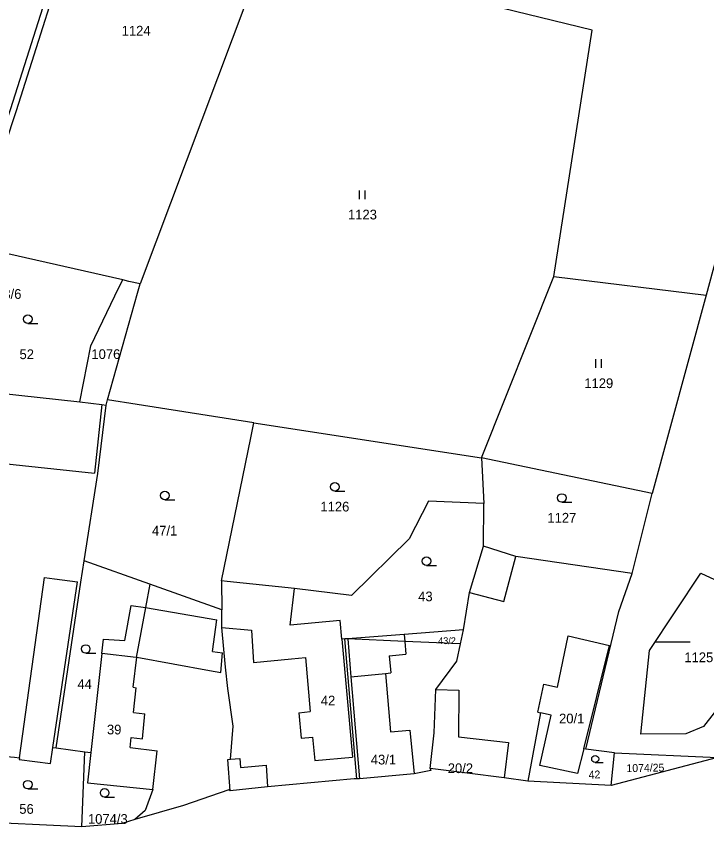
# Model space of a CAD drawing. Extents: x -746176 to -739709, y -1127410 to -1124482.
# Drawn here: x -742233.7 to -742113, y -1126052.3 to -1125910.5 of the extents above; entities that cross this region are included whole.
import ezdxf

# ---------------------------------------------------------------- set-up
doc = ezdxf.new("R2010")
doc.units = 0
for name, color, linetype in [('Hranice parcel', 7, 'Continuous'), ('Parcelní čísla', 7, 'Continuous'), ('Vnitřní kresba', 7, 'Continuous'), ('Značky kultur', 7, 'Continuous')]:
    doc.layers.add(name, color=color, linetype=linetype)

msp = doc.modelspace()

# ---------------------------------------------------------------- linework, layer by layer
at = {"layer": 'Hranice parcel'}
for p, q in [((-742190.21, -1125899.2), (-742212.05, -1125957.33)), ((-742110.2, -1125948.49), (-742113.1, -1125959.31)), ((-742215.07, -1125956.62), (-742241.51, -1125950.63)), ((-742152.36, -1125987.76), (-742139.76, -1125956.04)), ((-742139.76, -1125956.04), (-742113.1, -1125959.31)), ((-742113.1, -1125959.31), (-742122.54, -1125993.99)), ((-742246.94, -1125975.25), (-742222.55, -1125977.95)), ((-742217.96, -1125978.51), (-742217.71, -1125977.62)), ((-742192.16, -1125981.6), (-742152.36, -1125987.76)), ((-742122.54, -1125993.99), (-742152.36, -1125987.76)), ((-742152.36, -1125987.76), (-742151.94, -1125995.7)), ((-742126.05, -1126007.96), (-742122.54, -1125993.99)), ((-742152.03, -1126003.21), (-742151.94, -1125995.7)), ((-742210.31, -1126009.86), (-742221.81, -1126005.78)), ((-742197.79, -1126009.24), (-742197.78, -1126014.31)), ((-742197.78, -1126014.31), (-742210.31, -1126009.86)), ((-742156.03, -1126020.28), (-742155.5, -1126017.83)), ((-742174.18, -1126043.87), (-742176.24, -1126019.4)), ((-742156.03, -1126020.28), (-742165.79, -1126019.86)), ((-742226.7, -1126038.48), (-742221.69, -1126039.15)), ((-742222.2, -1126052.27), (-742221.69, -1126039.15)), ((-742221.69, -1126039.15), (-742220.66, -1126039.29)), ((-742129.13, -1126039.33), (-742134.12, -1126038.69)), ((-742129.74, -1126045.05), (-742129.13, -1126039.33)), ((-742129.13, -1126039.33), (-742111.14, -1126040.16)), ((-742111.14, -1126040.16), (-742129.74, -1126045.05)), ((-742148.42, -1126043.69), (-742161.35, -1126042.09)), ((-742144.3, -1126044.3), (-742148.42, -1126043.69)), ((-742129.74, -1126045.05), (-742144.3, -1126044.3))]:
    msp.add_line(p, q, dxfattribs=at)
for points in [[(-742241.51, -1125950.63), (-742233.66, -1125926.96), (-742223.23, -1125894.07), (-742218.91, -1125880.44), (-742217.69, -1125875.07), (-742216.33, -1125869.06)], [(-742239.87, -1125941.89), (-742234.61, -1125926.63), (-742224.19, -1125893.77)], [(-742139.76, -1125956.04), (-742133.02, -1125912.95), (-742184.93, -1125900.23)], [(-742222.55, -1125977.95), (-742220.67, -1125968.16), (-742215.73, -1125957.97), (-742215.07, -1125956.62)], [(-742212.05, -1125957.33), (-742213.99, -1125956.87), (-742215.07, -1125956.62)], [(-742217.71, -1125977.62), (-742212.49, -1125958.92), (-742212.05, -1125957.33)], [(-742222.55, -1125977.95), (-742218.7, -1125978.38), (-742217.96, -1125978.51)], [(-742192.16, -1125981.6), (-742212.57, -1125978.42), (-742217.71, -1125977.62)], [(-742221.81, -1126005.78), (-742219.41, -1125990.5), (-742217.96, -1125978.51)], [(-742197.79, -1126009.24), (-742192.7, -1125984.26), (-742192.16, -1125981.6)], [(-742151.94, -1125995.7), (-742161.62, -1125995.29), (-742165.01, -1126001.93), (-742175.08, -1126011.79), (-742185.07, -1126010.6)], [(-742155.5, -1126017.83), (-742154.46, -1126011.3), (-742152.03, -1126003.21)], [(-742126.05, -1126007.96), (-742146.39, -1126004.99), (-742152.03, -1126003.21)], [(-742226.7, -1126038.48), (-742222.39, -1126009.48), (-742221.81, -1126005.78)], [(-742134.12, -1126038.69), (-742128.4, -1126014.62), (-742126.05, -1126007.96)], [(-742102.49, -1126016.08), (-742109.85, -1126029.96), (-742113.56, -1126034.73), (-742116.68, -1126036.01), (-742124.54, -1126036.07), (-742122.99, -1126021.43), (-742114.02, -1126007.91), (-742106.36, -1126011.45), (-742102.49, -1126016.08)], [(-742185.07, -1126010.6), (-742196.8, -1126009.35), (-742197.79, -1126009.24)], [(-742210.31, -1126009.86), (-742211.09, -1126013.94), (-742212.75, -1126022.64), (-742218.71, -1126021.97), (-742220.66, -1126039.29)], [(-742176.24, -1126019.4), (-742176.77, -1126019.44), (-742177.07, -1126016.16), (-742185.84, -1126017), (-742185.07, -1126010.6)], [(-742196.32, -1126046.01), (-742196.68, -1126040.49), (-742196.21, -1126040.46), (-742195.76, -1126034.69), (-742196.68, -1126028.06), (-742197.1, -1126024.33), (-742197.78, -1126017.4), (-742197.78, -1126014.31)], [(-742155.5, -1126017.83), (-742165.88, -1126018.63), (-742175.74, -1126019.37), (-742176.24, -1126019.4)], [(-742165.79, -1126019.86), (-742175.74, -1126019.42), (-742176.24, -1126019.4)], [(-742160.34, -1126028.23), (-742156.69, -1126023.3), (-742156.03, -1126020.28)], [(-742161.35, -1126042.09), (-742160.66, -1126035.86), (-742160.34, -1126028.23)], [(-742160.34, -1126028.23), (-742156.31, -1126028.36), (-742156.37, -1126036.56), (-742147.63, -1126037.55), (-742148.42, -1126043.69)], [(-742134.12, -1126038.69), (-742134.51, -1126038.64), (-742135.58, -1126042.95), (-742142.18, -1126041.55), (-742140.2, -1126032.73), (-742142.09, -1126032.32), (-742144.3, -1126044.3)], [(-742240.91, -1126039.92), (-742239.93, -1126039.95), (-742239.83, -1126039.64), (-742234.01, -1126040.12), (-742233.11, -1126040.21), (-742233.15, -1126040.51), (-742227.7, -1126041.18), (-742227.29, -1126038.4), (-742226.7, -1126038.48)], [(-742220.66, -1126039.29), (-742221.25, -1126044.6), (-742209.84, -1126045.76), (-742211.16, -1126049.44), (-742212.94, -1126050.97)], [(-742222.2, -1126052.27), (-742242, -1126051.32), (-742240.91, -1126039.92)], [(-742161.35, -1126042.09), (-742161.2, -1126042.42), (-742164.15, -1126043.01), (-742173.72, -1126043.88), (-742174.18, -1126043.87)], [(-742174.18, -1126043.87), (-742174.65, -1126043.87), (-742189.75, -1126045.28), (-742196.32, -1126046.01)], [(-742196.32, -1126046.01), (-742196.53, -1126045.8), (-742204.43, -1126048.56), (-742212.94, -1126050.97)], [(-742212.94, -1126050.97), (-742215.19, -1126051.67), (-742222.2, -1126052.27)]]:
    msp.add_lwpolyline(points, dxfattribs=at)
at = {"layer": 'Vnitřní kresba'}
for p, q in [((-742218.7, -1125978.38), (-742220, -1125990.44)), ((-742240.74, -1125988.18), (-742220, -1125990.44)), ((-742148.47, -1126012.88), (-742146.39, -1126004.99)), ((-742233.11, -1126040.21), (-742228.77, -1126008.67)), ((-742228.77, -1126008.67), (-742227.02, -1126008.89)), ((-742227.29, -1126038.4), (-742222.99, -1126009.4)), ((-742227.02, -1126008.89), (-742222.99, -1126009.4)), ((-742154.46, -1126011.3), (-742148.47, -1126012.88)), ((-742214.69, -1126019.69), (-742213.59, -1126013.59)), ((-742213.59, -1126013.59), (-742211.09, -1126013.94)), ((-742211.09, -1126013.94), (-742198.6, -1126016.1)), ((-742199.41, -1126021.59), (-742198.6, -1126016.1)), ((-742197.78, -1126017.4), (-742192.59, -1126017.86)), ((-742192.59, -1126017.86), (-742192.2, -1126023.56)), ((-742218.71, -1126021.97), (-742218.42, -1126019.45)), ((-742218.42, -1126019.45), (-742214.69, -1126019.69)), ((-742176.77, -1126019.44), (-742174.94, -1126040.08)), ((-742175.74, -1126019.42), (-742175.19, -1126026.04)), ((-742165.88, -1126018.63), (-742165.79, -1126019.86)), ((-742139.09, -1126027.84), (-742137.21, -1126018.89)), ((-742137.21, -1126018.89), (-742130.02, -1126020.54)), ((-742165.79, -1126019.86), (-742165.62, -1126022.05)), ((-742134.51, -1126038.64), (-742130.02, -1126020.54)), ((-742199.41, -1126021.59), (-742197.64, -1126021.85)), ((-742197.95, -1126025.26), (-742197.64, -1126021.85)), ((-742168.51, -1126022.39), (-742165.62, -1126022.05)), ((-742168.51, -1126022.39), (-742168.22, -1126025.37)), ((-742213.26, -1126027.87), (-742212.63, -1126022.63)), ((-742212.75, -1126022.64), (-742212.63, -1126022.63)), ((-742212.63, -1126022.63), (-742199.91, -1126024.91)), ((-742192.2, -1126023.56), (-742185.56, -1126022.89)), ((-742185.56, -1126022.89), (-742183.15, -1126022.65)), ((-742183.15, -1126022.65), (-742182.29, -1126032.13)), ((-742199.91, -1126024.91), (-742197.95, -1126025.26)), ((-742175.19, -1126026.04), (-742169.17, -1126025.46)), ((-742175.19, -1126026.04), (-742173.72, -1126043.88)), ((-742169.17, -1126025.46), (-742168.22, -1126025.37)), ((-742169.17, -1126025.46), (-742168.27, -1126035.66)), ((-742213.26, -1126027.87), (-742212.72, -1126027.94)), ((-742213.19, -1126032.3), (-742212.72, -1126027.94)), ((-742142.53, -1126032.23), (-742141.46, -1126027.32)), ((-742141.46, -1126027.32), (-742139.09, -1126027.84)), ((-742213.19, -1126032.3), (-742211.19, -1126032.49)), ((-742184.31, -1126032.31), (-742182.29, -1126032.13)), ((-742184.31, -1126032.31), (-742183.89, -1126036.77)), ((-742142.53, -1126032.23), (-742142.09, -1126032.32)), ((-742211.62, -1126036.88), (-742211.19, -1126032.49)), ((-742183.89, -1126036.77), (-742181.89, -1126036.58)), ((-742181.89, -1126036.58), (-742181.52, -1126040.69)), ((-742168.27, -1126035.66), (-742164.88, -1126035.36)), ((-742164.88, -1126035.36), (-742164.15, -1126043.01)), ((-742213.77, -1126038.4), (-742213.6, -1126036.68)), ((-742213.6, -1126036.68), (-742211.62, -1126036.88)), ((-742213.77, -1126038.4), (-742209.07, -1126038.97)), ((-742209.84, -1126045.76), (-742209.07, -1126038.97)), ((-742196.21, -1126040.46), (-742194.61, -1126040.35)), ((-742194.61, -1126040.35), (-742194.47, -1126041.89)), ((-742181.52, -1126040.69), (-742174.94, -1126040.08)), ((-742194.47, -1126041.89), (-742190.03, -1126041.47)), ((-742190.03, -1126041.47), (-742189.75, -1126045.28))]:
    msp.add_line(p, q, dxfattribs=at)
at = {"layer": 'Značky kultur'}
for p, q in [((-742173.711, -1125942.49), (-742173.711, -1125940.99)), ((-742172.71, -1125942.49), (-742172.71, -1125940.99)), ((-742231.663, -1125964.22), (-742229.913, -1125964.22)), ((-742132.411, -1125971.99), (-742132.411, -1125970.49)), ((-742131.41, -1125971.99), (-742131.41, -1125970.49)), ((-742178.013, -1125993.57), (-742176.263, -1125993.57)), ((-742207.713, -1125995.08), (-742205.963, -1125995.08)), ((-742138.343, -1125995.51), (-742136.593, -1125995.51)), ((-742161.993, -1126006.58), (-742160.243, -1126006.58)), ((-742121.909, -1126019.93), (-742115.909, -1126019.93)), ((-742221.543, -1126021.92), (-742219.793, -1126021.92)), ((-742132.504, -1126041.02), (-742131.087, -1126041.02)), ((-742231.673, -1126045.65), (-742229.923, -1126045.65)), ((-742218.233, -1126047.07), (-742216.483, -1126047.07))]:
    msp.add_line(p, q, dxfattribs=at)
for centre, radius in [((-742231.663, -1125963.47), 0.75), ((-742178.013, -1125992.82), 0.75), ((-742207.713, -1125994.33), 0.75), ((-742138.343, -1125994.76), 0.75), ((-742161.993, -1126005.83), 0.75), ((-742221.543, -1126021.17), 0.75), ((-742132.504, -1126040.412), 0.607), ((-742231.673, -1126044.9), 0.75), ((-742218.233, -1126046.32), 0.75)]:
    msp.add_circle(centre, radius, dxfattribs=at)

# ---------------------------------------------------------------- texts
at = {"layer": 'Parcelní čísla'}
for s, height, p in [('1124', 1.7, (-742215.257, -1125913.88)), ('1123', 1.7, (-742175.707, -1125946.04)), ('58/6', 1.7, (-742237.2, -1125959.933)), ('52', 1.7, (-742233.112, -1125970.47)), ('1076', 1.7, (-742220.547, -1125970.45)), ('1129', 1.7, (-742134.407, -1125975.54)), ('1126', 1.7, (-742180.527, -1125997.12)), ('1127', 1.7, (-742140.857, -1125999.07)), ('47/1', 1.7, (-742209.961, -1126001.33)), ('43', 1.7, (-742163.442, -1126012.83)), ('43/2', 1.19, (-742159.95, -1126020.315)), ('1125', 1.7, (-742116.927, -1126023.48)), ('44', 1.7, (-742222.992, -1126028.17)), ('42', 1.7, (-742180.452, -1126031.04)), ('20/1', 1.7, (-742138.821, -1126034.18)), ('39', 1.7, (-742217.832, -1126036.11)), ('43/1', 1.7, (-742171.72, -1126041.37)), ('20/2', 1.7, (-742158.271, -1126042.88)), ('56', 1.7, (-742233.152, -1126050)), ('1074/3', 1.7, (-742221.155, -1126051.75))]:
    msp.add_text(s, height=height, dxfattribs=at).set_placement(p)
for s, rotation, p in [('1074/25', 1, (-742127.03, -1126042.708)), ('42', 2, (-742133.627, -1126043.855))]:
    msp.add_text(s, height=1.37, rotation=rotation, dxfattribs=at).set_placement(p)

doc.saveas('drawing.dxf')
